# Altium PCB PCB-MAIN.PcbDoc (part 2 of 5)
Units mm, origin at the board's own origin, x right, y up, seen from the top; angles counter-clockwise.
Board outline 110 x 75 mm, 8 copper layers (F.Cu, In1.Cu, In2.Cu, In3.Cu, In4.Cu, In5.Cu, In6.Cu, B.Cu); 251 components, 185 nets, 1143 pads, 853 vias.
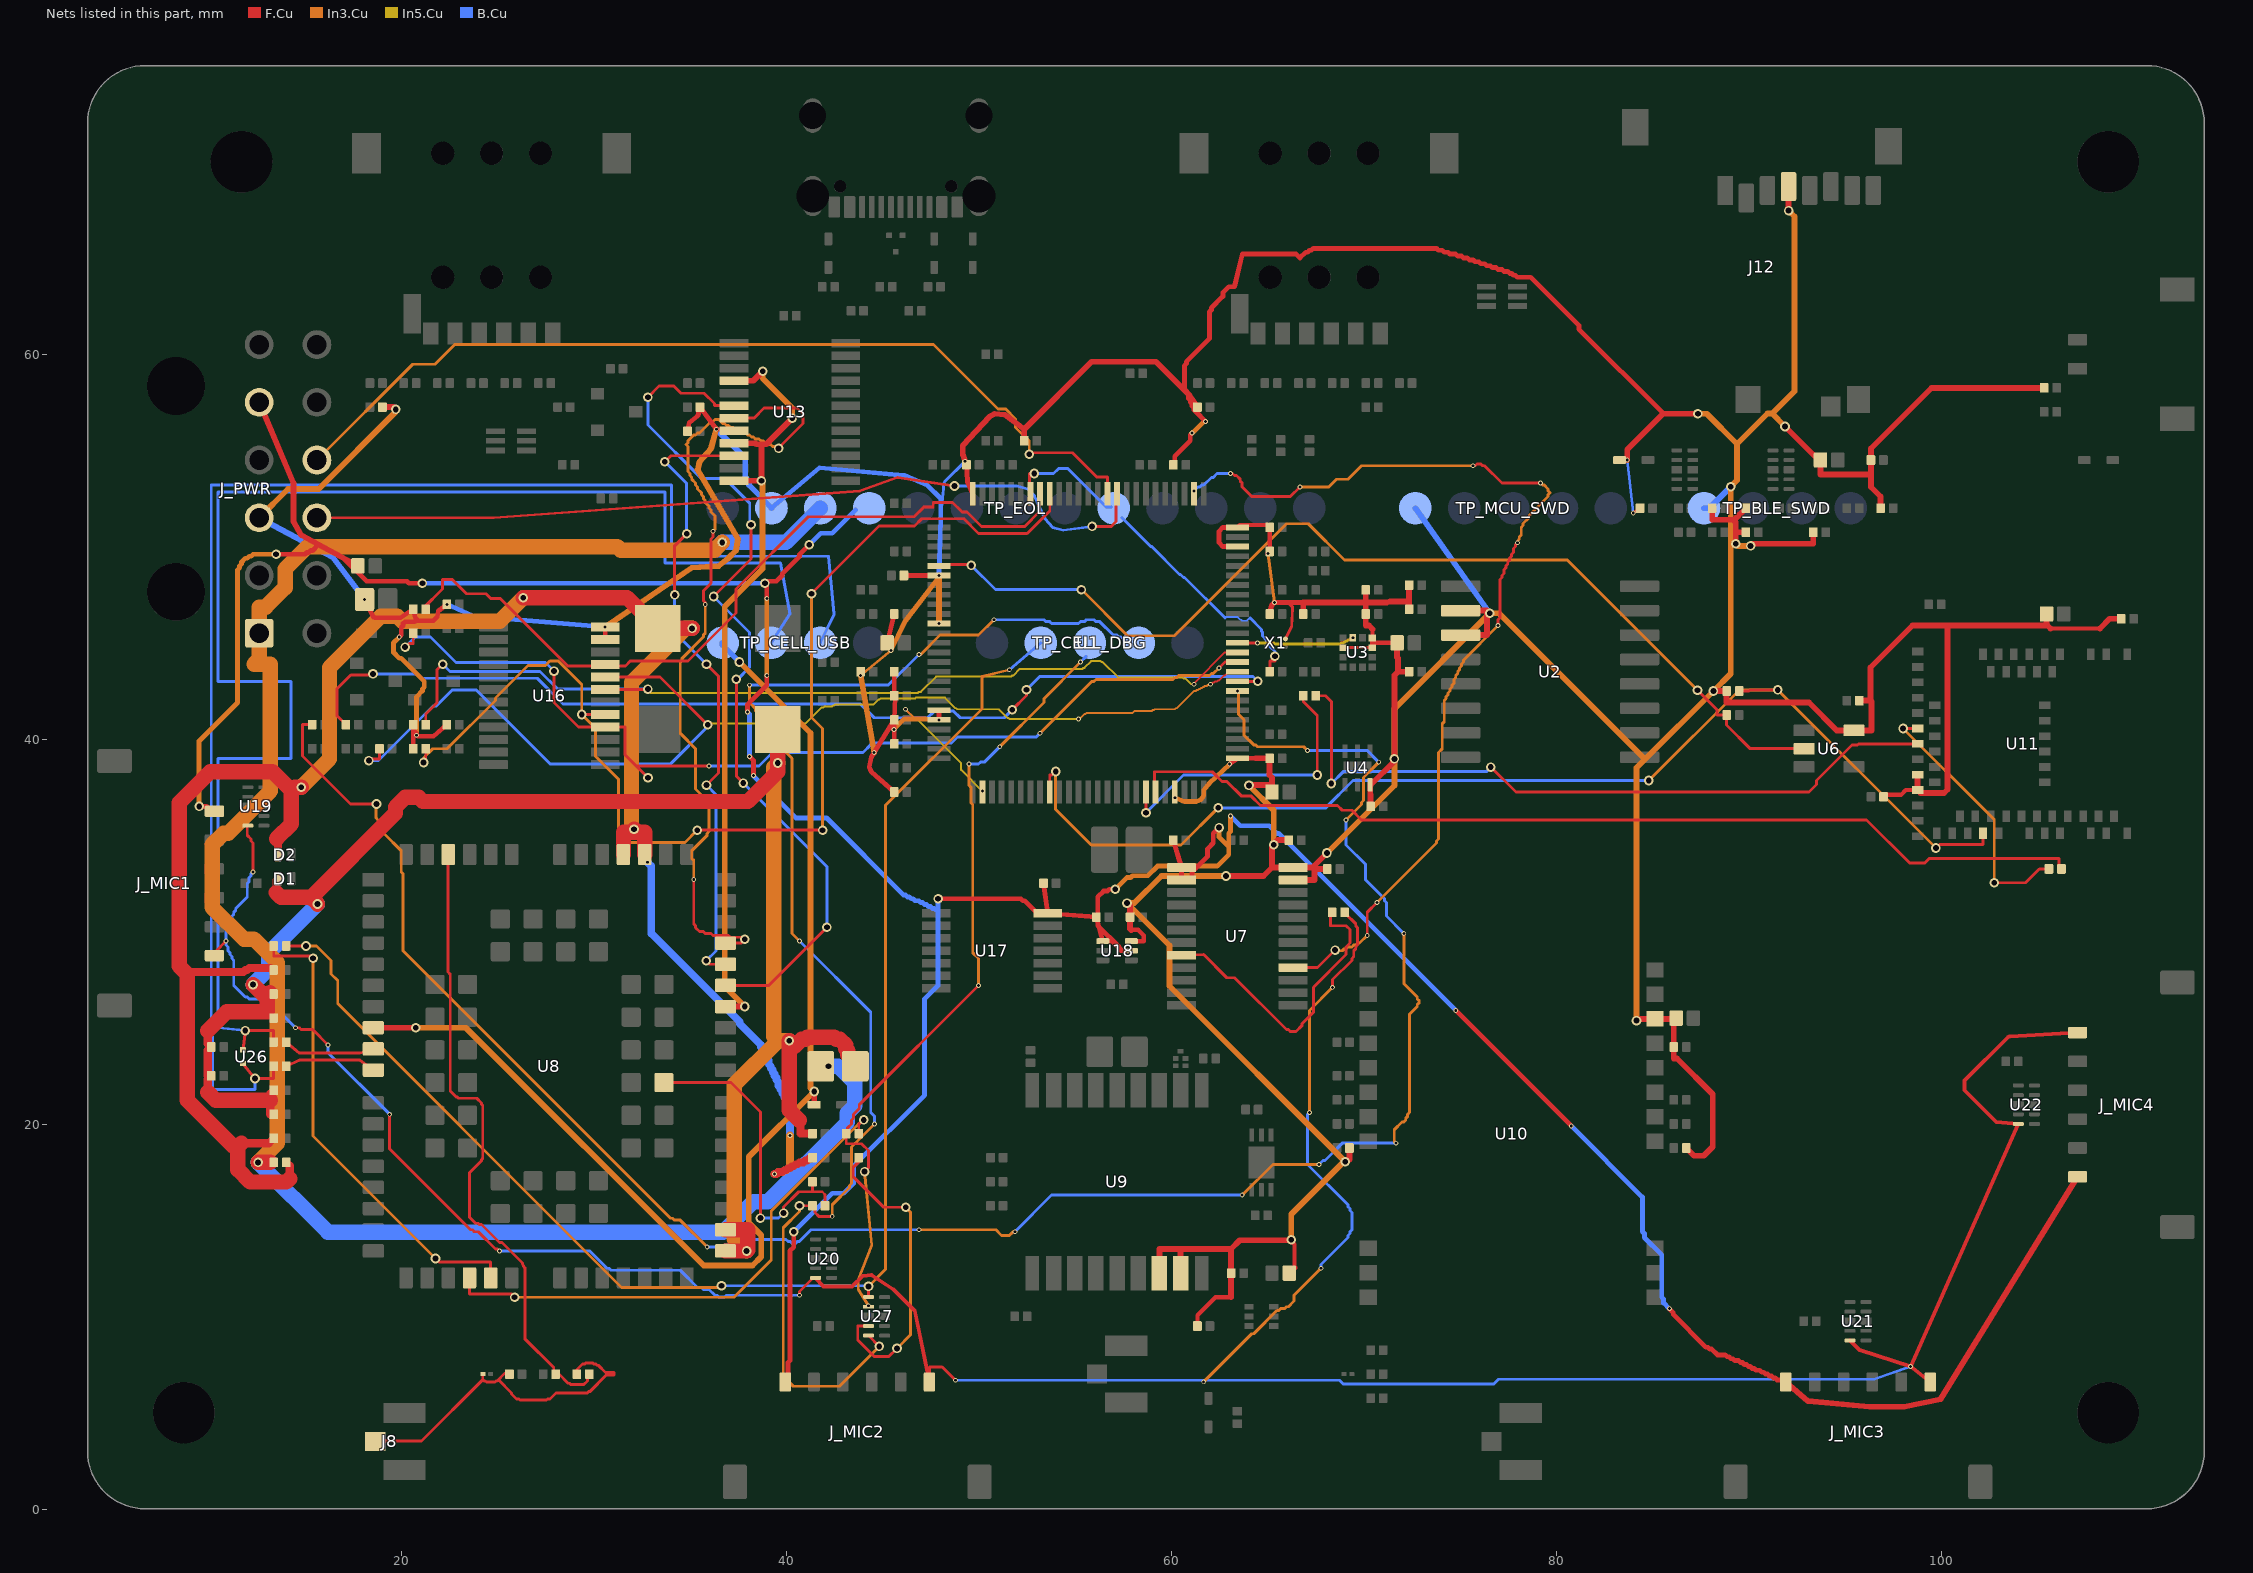
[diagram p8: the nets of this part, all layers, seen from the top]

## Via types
v1: diameter 0.5, hole 0.3, F.Cu to B.Cu, tented both sides, 579 vias
v2: diameter 0.25, hole 0.15, F.Cu to B.Cu, tented both sides, 274 vias

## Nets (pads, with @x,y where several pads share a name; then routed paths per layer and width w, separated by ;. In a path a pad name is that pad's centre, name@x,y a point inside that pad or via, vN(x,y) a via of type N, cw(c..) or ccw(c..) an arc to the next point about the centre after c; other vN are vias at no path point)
1V8_MIC: C20.1 C27.1 C30.1 C31.1 J_MIC1.1 J_MIC2.1 J_MIC3.1 J_MIC4.1 J_PWR.5 TP_EOL.4 U7.1 U7.2 U17.14 U18.1 U18.5 | length 207.4
  F.Cu w0.25: v1(9.485,36.525) 9.885,36.525 J_MIC1.1@9.985,36.425 ; v1(13.485,49.625) 14.985,49.625 15.085,49.725 15.185,49.725 15.285,49.825 15.385,49.825 15.685,50.125 ; 16.985,49.425 18.185,48.225 20.285,48.225 20.385,48.125 v1(21.085,48.125) ; v2(37.985,41.425) 37.985,41.825 38.985,42.825 v2(38.985,43.325) ; v2(38.085,39.125) 38.285,38.925 v2(38.285,38.125) ; v1(38.885,48.125) v1@38.985,48.225 ; v2(38.985,47.325) v1@38.985,48.225 ; J_MIC2.1@40.085,6.925 40.085,7.625 40.185,7.725 40.185,13.425 40.385,13.625 v1(40.385,14.425) ; v1(41.185,50.125) 40.685,49.625 40.685,49.525 39.785,48.625 39.785,48.525 39.485,48.225 v1@38.985,48.225 ; v1(47.885,31.725) 52.185,31.725 52.285,31.625 52.385,31.625 U17.14@52.985,31.025 ; C30.1@53.36,32.525 U17.14@53.585,30.975 C31.1@56.11,30.775 U18.1@56.445,29.525 56.945,29.525 57.445,29.025 U18.5@57.925,29.025 ; v1(57.085,32.225) 56.785,32.225 56.685,32.125 56.485,32.125 56.185,31.825 56.185,30.325 57.285,29.225 57.285,29.125 57.385,29.025 57.485,29.025 ; C27.1@60.11,34.775 U7.1@60.535,33.35 U7.2@60.535,32.7 ; U7.2@61.085,32.725 61.085,33.125 61.885,33.925 61.885,34.325 62.185,34.625 62.185,35.125 v1(62.485,35.425) ; v2(74.785,25.925) v2(80.785,19.925) ; v2(85.885,10.425) 86.085,10.225 86.085,10.125 87.785,8.425 87.885,8.425 87.985,8.325 88.085,8.325 88.385,8.025 88.785,8.025 88.885,7.925 88.985,7.925 89.085,7.825 89.185,7.825 89.285,7.725 89.485,7.725 89.585,7.625 89.685,7.625 89.785,7.525 89.885,7.525 89.985,7.425 90.085,7.425 90.185,7.325 90.285,7.325 90.385,7.225 90.585,7.225 90.685,7.125 90.785,7.125 90.885,7.025 90.985,7.025 91.085,6.925 91.185,6.925 91.285,6.825 91.385,6.825 91.485,6.725 91.685,6.725 J_MIC3.1@91.785,6.625
  F.Cu w0.3: J_PWR.5@12.605,57.525 14.385,53.325 14.385,51.325 14.785,50.625 C20.1@17.735,49.025 ; J_MIC3.1@91.935,6.615 93.085,5.625 96.285,5.325 98.085,5.325 99.985,5.725 J_MIC4.1@107.095,17.275
  In3.Cu w0.25: v1(9.485,36.525) 9.485,39.925 11.485,41.925 11.485,48.825 11.585,48.925 11.585,49.025 11.685,49.125 11.685,49.225 11.885,49.425 11.985,49.425 12.085,49.525 12.185,49.525 12.285,49.625 v1(13.485,49.625) ; v2(38.985,43.325) v2(38.985,47.325) ; v1(57.085,32.225) 57.685,32.825 57.885,32.825 57.985,32.925 58.785,32.925 59.285,33.425 62.385,33.425 62.985,34.025 62.985,34.425 ; v1(62.485,35.425) 62.485,34.925 62.985,34.425 ; v2(63.085,36.025) 63.085,35.225 62.985,35.125 62.985,34.425
  B.Cu w0.25: v1(21.085,48.125) v1(38.885,48.125) ; v2(37.985,41.425) 38.085,41.325 v2(38.085,39.125) ; v2(38.285,38.125) 40.485,35.925 42.085,35.925 46.085,31.925 46.185,31.925 46.285,31.825 46.385,31.825 46.485,31.725 46.585,31.725 46.685,31.625 46.885,31.625 46.985,31.525 47.085,31.525 47.185,31.425 47.285,31.425 47.385,31.325 47.485,31.325 47.585,31.225 47.685,31.225 47.785,31.125 47.885,31.125 ; v1(40.385,14.425) 42.385,16.425 42.985,16.425 43.485,16.925 43.485,17.825 47.185,21.525 47.185,26.525 47.885,27.225 v1(47.885,31.725) ; v1(41.185,50.125) 41.785,50.725 42.385,50.725 TP_EOL.4@43.585,51.925 ; v2(63.085,36.025) 63.585,35.525 65.085,35.525 65.485,35.125 65.585,35.125 v2(74.785,25.925) ; v2(80.785,19.925) 84.485,16.225 84.485,14.425 84.585,14.325 84.585,14.125 85.485,13.225 85.485,11.025 85.585,10.925 85.585,10.725 v2(85.885,10.425)
3V3_DIGITAL: C1.1 C2.1 C3.1 C4.1 C5.1 C6.1 C7.1 C8.1 C9.1 C10.1 C11.1 C12.1 C13.1 C19.1 C21.1 C22.1 C23.1 C24.1 C25.1 C26.1 C28.1 C29.1 C32.1 C34.1 C35.1 C49.1 C60.1 C61.1 C62.1 C66.1 C67.1 C71.1 C72.1 C73.1 C74.1 C75.1 D11.1 J12.4 J_PWR.3 R1.1 R4.1 R6.1 R7.1 R13.1 R14.1 R28.1 R32.1 R33.1 R44.1 R48.1 R49.1 R67.1 R68.1 R76.1 R78.1 R85.1 R86.1 R87.1 R88.1 R89.1 R90.1 R99.1 TP_BLE_SWD.1 TP_EOL.2 TP_MCU_SWD.1 U1.6 U1.11 U1.20 U1.21 U1.27 U1.47 U1.51 U1.73 U1.75 U1.100 U2.2 U2.3 U3.2 U3.9 U3.10 U4.3 U6.5 U7.23 U7.24 U9.7 U9.8 U10.9 U11.28 U11.30 U13.8 U16.23 U16.24 U18.6 X1.3 | length 470.8
  F.Cu w0.15: v2(43.86,43.325) R14.1@43.86,43.525 ; C6.1@45.235,45.025 v2(45.435,44.625) ; R1.1@65.11,46.525 65.31,47.025 65.41,47.075 66.11,47.075 66.31,46.875 66.26,45.875 X1.3@65.935,45.23 ; U3.2@68.922,44.775 U3.9@70.447,44.775 ; v2(84.01,51.775) R90.1@84.36,52.025
  F.Cu w0.225: U18.6@57.925,29.525 58.575,29.525 58.575,29.817 58.282,30.11 57.925,30.11 ; C62.1@61.36,9.525 61.36,10.09 62.295,11.025 63.11,11.025 ; U1.51@63.435,39.025 64.349,39.025 64.387,39.025 ; U1.75@63.435,51.025 63.56,51.15 64.985,51.15 C4.1@65.11,51.025 65.11,50.34 C12.1@65.11,49.775 ; v1@66.207,13.978 66.407,13.777 C61.1@66.407,12.548 ; v1@66.219,14.002 v1(66.231,14.002) ; U3.9@70.447,44.775 70.447,45.025 ; 70.46,45.737 70.46,45.288 U3.10@70.447,45.275 70.447,45.025 ; 71.2,47.124 71.31,47.124 71.36,47.175 ; C24.1@71.735,45.025 70.447,45.025 ; R78.1@97.01,37.125 97.921,37.125 98.171,37.375 U11.30@98.785,37.375 ; 105.684,45.774 108.26,45.774
  F.Cu w0.25: v2(18.085,47.275) 18.535,46.375 18.635,46.325 19.935,46.325 R32.1@20.61,46.775 20.71,46.325 20.86,46.175 ; v2(19.885,45.325) 19.985,45.425 19.985,45.825 20.085,45.925 20.085,46.025 20.185,46.125 20.685,46.125 20.785,46.225 20.86,46.175 ; R28.1@20.61,39.525 R33.1@20.61,40.775 20.66,40.425 ; v2(20.785,40.225) 20.785,40.325 20.66,40.425 ; C35.1@22.36,40.775 21.66,40.175 20.86,40.175 20.66,40.425 ; v2(22.36,47.025) 21.91,46.675 21.86,46.375 21.66,46.175 20.86,46.175 ; U16.23@30.585,45.2 v2(30.585,45.85) ; C49.1@34.86,56.025 34.96,56.475 35.41,56.825 R44.1@35.51,57.275 v2(36.36,56.125) U13.8@37.285,56.05 ; C6.1@45.235,45.025 C1.1@45.61,46.525 ; v2(45.585,40.525) C8.1@45.61,41.025 ; C2.1@45.61,37.275 44.41,38.325 44.31,38.575 44.41,39.075 C8.1@45.61,41.025 ; C10.1@45.61,39.775 C8.1@45.61,41.025 ; C11.1@45.61,43.525 C9.1@45.61,42.275 45.66,42.225 C8.1@45.61,41.025 ; C7.1@46.11,48.525 v2(47.935,48.525) ; v2(47.935,41.025) U1.20@47.935,41.525 ; C5.1@49.36,54.275 49.41,53.425 U1.100@49.685,52.775 ; R4.1@60.185,54.325 60.185,54.725 60.985,55.525 60.985,55.825 v2(61.085,55.925) ; R49.1@61.285,57.425 R49.1@61.285,57.025 ; v2(61.785,56.525) R49.1@61.285,57.025 ; v2(63.035,38.725) U1.51@63.435,39.025 ; U1.73@63.435,50.025 62.685,50.025 62.485,50.225 62.485,50.825 62.685,51.025 U1.75@63.435,51.025 ; v2(65.035,49.675) C12.1@65.11,49.775 ; R1.1@65.11,46.525 65.21,46.977 v2(65.36,47.127) 66.86,47.127 ; 85.585,56.925 81.185,61.325 81.185,61.525 78.685,64.025 77.985,64.025 77.885,64.125 77.785,64.125 77.685,64.225 77.585,64.225 77.485,64.325 77.285,64.325 77.185,64.425 76.985,64.425 76.885,64.525 76.685,64.525 76.585,64.625 76.385,64.625 76.285,64.725 76.085,64.725 75.985,64.825 75.785,64.825 75.685,64.925 75.485,64.925 75.385,65.025 75.185,65.025 75.085,65.125 74.885,65.125 74.785,65.225 74.485,65.225 74.385,65.325 74.185,65.325 74.085,65.425 73.885,65.425 73.785,65.525 67.385,65.525 67.285,65.425 67.185,65.425 67.085,65.325 66.985,65.325 66.685,65.025 66.485,65.225 63.685,65.225 63.285,63.525 62.985,63.525 62.685,63.225 62.685,63.025 62.085,62.425 62.085,62.325 61.985,62.225 61.985,60.825 60.785,59.625 60.785,59.525 60.685,59.425 60.685,58.225 60.785,58.125 60.785,58.025 60.885,57.925 60.885,57.725 60.985,57.625 60.985,57.525 61.085,57.425 61.085,57.325 61.185,57.225 61.185,57.125 R49.1@61.285,57.025
  F.Cu w0.3: R48.1@19.01,57.275 19.587,57.275 v1(19.704,57.158) ; C5.1@49.36,54.275 49.16,54.827 49.16,55.277 50.56,56.777 50.81,56.927 51.36,56.877 52.36,56.127 ; R6.1@52.36,55.525 52.36,56.127 ; v1(57.698,31.503) 57.825,31.377 57.86,31.377 C32.1@57.86,30.775 57.86,30.173 57.861,30.173 57.925,30.11 ; U9.7@59.385,12.275 59.385,13.527 60.485,13.527 ; U9.8@60.485,12.275 60.485,13.527 ; R49.1@61.36,57.275 60.955,57.877 59.205,59.627 55.86,59.627 52.36,56.127 ; v1(62.845,32.912) 64.795,32.912 65.233,33.35 ; 63.11,11.025 C60.1@63.11,12.275 63.11,13.527 ; v1(64.041,37.616) 64.062,37.638 C13.1@65.235,37.638 ; 64.387,39.025 64.533,39.025 C3.1@65.11,39.025 65.11,38.152 65.235,38.027 C13.1@65.235,37.638 ; C13.1@65.235,37.275 C13.1@65.235,37.638 ; C28.1@66.11,34.775 65.533,34.775 65.329,34.571 v1(65.329,34.533) 65.233,34.437 65.233,33.35 ; C61.1@66.135,12.275 C61.1@66.407,12.548 ; v1@66.219,14.002 66.207,13.99 66.207,13.978 63.561,13.978 63.11,13.527 ; U7.23@66.335,32.7 67.437,32.7 67.437,33.275 ; R13.1@66.86,46.525 66.86,47.127 70.11,47.127 ; v1(68.089,34.104) 67.335,33.351 ; C29.1@68.11,33.275 67.437,33.275 ; v1(69.042,18.059) 69.156,18.173 69.26,18.173 R67.1@69.26,18.775 ; C25.1@70.11,47.775 70.11,47.127 ; C26.1@70.36,36.525 70.36,37.127 70.335,37.152 U4.3@70.335,37.66 70.386,37.66 71.595,38.869 v1(71.595,38.995) 71.595,43.337 71.783,43.525 ; 70.46,45.737 70.274,45.923 70.11,45.923 C23.1@70.11,46.525 70.11,47.127 ; 71.2,47.124 71.197,47.127 70.11,47.127 ; 71.36,47.175 72.36,47.175 ; C24.1@71.735,45.025 71.735,44.273 71.783,44.225 71.783,43.525 ; R7.1@72.36,43.525 71.783,43.525 ; C21.1@72.36,46.775 72.36,47.175 ; C22.1@72.36,48.025 72.36,47.175 ; U2.3@75.035,45.43 76.412,45.43 v1@76.412,46.7 ; U2.2@75.035,46.7 v1@76.412,46.7 ; v1(76.555,46.56) 76.552,46.56 v1@76.412,46.7 ; D11.1@83.295,54.525 v2(83.695,54.525) 83.695,55.077 85.553,56.935 v1(87.368,56.935) ; v1(84.178,25.397) 84.245,25.397 84.333,25.485 U10.9@85.135,25.485 C67.1@85.937,25.485 ; C67.1@86.235,25.525 85.977,25.525 C67.1@85.937,25.485 ; R68.1@86.76,18.775 87.162,18.373 87.672,18.373 88.143,18.844 88.143,21.564 86.284,23.423 86.11,23.423 C66.1@86.11,24.025 86.11,25.312 C67.1@85.937,25.485 ; R86.1@88.11,52.025 88.11,51.423 89.206,51.423 89.232,51.397 ; v1(88.173,42.525) 88.283,42.525 R76.1@88.86,42.525 88.86,41.923 93.135,41.923 94.583,40.475 U6.5@95.485,40.475 96.387,40.475 96.387,41.975 96.337,42.025 ; v1(89.335,50.172) 89.337,50.174 89.337,50.775 ; R87.1@89.86,50.775 89.337,50.775 ; R89.1@89.86,52.025 89.232,51.397 ; v1(90.105,50.062) 90.216,50.173 93.36,50.173 R88.1@93.36,50.775 ; v1(91.894,56.268) 93.636,54.525 C75.1@93.735,54.525 93.735,53.773 96.36,53.773 ; v1(92.08,67.486) J12.4@92.08,68.735 ; C73.1@95.76,42.025 96.337,42.025 ; R85.1@96.86,52.025 96.86,52.627 96.36,53.127 96.36,53.773 ; R78.1@97.01,37.025 R78.1@97.01,37.125 ; U11.28@98.785,38.175 U11.30@98.785,37.375 98.937,37.223 100.159,37.223 100.337,37.402 100.337,45.923 ; R99.1@105.36,58.275 99.508,58.275 96.36,55.127 C74.1@96.36,54.525 96.36,53.773 ; C72.1@105.485,46.525 105.485,45.923 ; 105.684,45.774 105.536,45.923 105.485,45.923 ; 108.26,45.774 108.761,46.275 C71.1@109.36,46.275 ; 60.485,13.527 63.11,13.527 ; 65.233,33.35 U7.24@66.335,33.35 67.261,33.35 67.335,33.35 ; 67.335,33.35 67.437,33.35 67.437,33.275 ; 89.232,51.397 89.337,51.293 89.337,50.775 ; 96.337,42.025 96.337,43.741 98.518,45.923 100.337,45.923 ; 100.337,45.923 105.485,45.923
  In3.Cu w0.1: v2(46.185,41.575) 46.685,41.075
  In3.Cu w0.15: v2(43.86,43.325) v2(45.435,44.625) ; v2(65.035,49.675) v2(65.36,47.127)
  In3.Cu w0.25: v2(19.885,45.325) 19.585,45.025 19.585,44.525 19.885,44.225 19.985,44.225 21.185,43.025 21.185,42.725 21.085,42.625 21.085,42.525 20.785,42.225 v2(20.785,40.225) ; v2(45.435,44.625) 46.185,46.175 47.885,48.375 v2(47.935,48.525) ; v2(45.585,40.525) 46.135,41.075 46.335,41.075 47.235,41.075 v2(47.935,41.025) ; v2(60.185,36.975) 60.685,36.775 61.285,36.775 61.535,36.875 61.685,37.075 61.685,37.375 61.985,37.725 v2(63.035,38.725) ; v2(61.085,55.925) 61.685,56.525 v2(61.785,56.525)
  In3.Cu w0.3: J_PWR.3@12.605,51.525 14.105,53.025 15.696,53.025 19.704,57.034 v1(19.704,57.158) ; v2(30.585,45.85) 35.085,48.925 36.485,49.025 36.985,49.425 37.385,49.825 37.485,50.425 35.385,54.025 35.485,54.425 36.085,55.125 v2(36.36,56.125) ; v2(43.86,43.325) v2(44.562,39.322) ; v2(47.935,46.025) v2(47.935,48.525) ; v1(62.845,32.912) 59.488,32.912 58.079,31.503 v1(57.698,31.503) 59.91,29.291 59.91,27.188 68.96,18.138 v1@68.96,18.059 ; v1(64.041,37.616) 65.329,36.327 v1(65.329,34.533) ; v1(66.231,14.002) 66.231,15.33 v1@68.96,18.059 ; v1(68.089,34.104) 71.595,37.611 v1(71.595,38.995) 71.595,41.6 v1(76.555,46.56) 77.03,46.56 84.619,38.971 ; v1(69.042,18.059) v1@68.96,18.059 ; v1(84.178,25.397) 84.178,38.53 84.619,38.971 ; v1(87.368,56.935) 87.826,56.935 89.405,55.356 ; v1(90.105,50.062) 89.445,50.062 v1(89.335,50.172) 89.072,50.172 ; v1(91.894,56.268) 91.225,56.936 ; v1(92.08,67.486) 92.391,67.175 92.391,58.102 91.225,56.936 ; 84.619,38.971 v1(88.173,42.525) 89.072,43.424 89.072,50.172 ; 89.072,50.172 v1(89.072,53.139) 89.405,53.472 89.405,55.356 ; 89.405,55.356 90.986,56.936 91.225,56.936
  In5.Cu w0.1: v2(46.185,41.575) 46.735,41.025 46.835,41.025 49.085,38.775 49.085,38.425 v2(50.185,37.325)
  B.Cu w0.15: 48.025,51.525 48.185,53.325 48.235,53.425 v2(49.292,54.463) ; v2(83.695,54.525) v2(84.01,51.775)
  B.Cu w0.25: v2(22.36,47.025) 23.685,46.425 v2(30.585,45.85) ; TP_EOL.2@39.225,52.025 41.725,54.125 46.125,53.725 47.325,53.225 48.025,52.525 48.025,51.525 v2(47.935,48.525)
  B.Cu w0.3: J_PWR.3@12.605,51.525 16.435,49.475 v2(18.085,47.275) ; v2(36.36,56.125) 37.86,54.625 37.86,53.625 38.06,53.425 38.06,53.225 TP_EOL.2@39.225,52.025 ; TP_MCU_SWD.1@72.685,52.025 v1(76.555,46.56) ; TP_BLE_SWD.1@87.685,52.025 87.958,52.025 v1(89.072,53.139)
3V8_MODEM: FB1.1 J_PWR.1 R42.1 TP_EOL.3 | length 104.5
  F.Cu w0.4: R42.1@13.183,18.025 R42.1@13.36,18.025
  F.Cu w0.8: v1(12.549,18.025) R42.1@13.183,18.025
  In3.Cu w0.8: v1(12.549,18.025) 13.553,19.03 13.553,28.408 12.329,29.632 11.814,29.632 10.165,31.282 10.165,34.534 10.753,35.123 10.996,35.123 12.347,36.474 13.185,37.325 13.185,43.915 12.347,43.915 12.605,44.172 J_PWR.1@12.605,45.525 12.605,46.878 12.943,46.878 13.958,47.892 13.958,48.862 15.12,50.025 31.215,50.025 31.395,49.845 36.268,49.845 v1(36.666,50.243)
  B.Cu w0.8: v1(12.549,18.025) 16.173,14.401 36.714,14.401 38.299,15.986 39.039,15.986 43.165,20.112 43.165,20.589 43.555,20.979 43.555,22.156 42.685,23.025 v1(42.185,23.025) ; v1(36.666,50.243) 39.983,50.243 TP_EOL.3@41.765,52.025
3V8_MODEM_BB: C36.1 C37.1 C38.1 C39.1 C40.1 C41.1 C42.1 C43.1 D1.1 FB1.2 U8.32 U8.33 | length 93
  F.Cu w0.4: C37.1@9.934,22.35 C37.1@10.11,22.525 C37.1@9.935,22.525 ; C38.1@9.934,23.85 C38.1@10.11,24.025 C38.1@9.934,24.201 ; 13.022,25.863 C40.1@13.36,25.525 ; C39.1@13.184,21.6 C39.1@13.36,21.775 ; C41.1@13.185,20.525 C41.1@13.36,20.525 ; C43.1@13.227,26.775 C43.1@13.36,26.775 ; 40.661,20.224 40.733,20.152 40.733,19.525 C42.1@41.36,19.525
  F.Cu w0.401: 13.484,32.053 13.484,32.674 D1.1@13.585,32.775
  F.Cu w0.45: 9.934,21.673 C37.1@9.934,22.35 ; C37.1@9.934,22.525 C38.1@9.934,23.85 ; C38.1@9.934,24.201 9.934,24.877 ; C43.1@13.152,26.85 C43.1@13.227,26.775 ; C41.1@13.184,20.525 13.184,21.264 C39.1@13.184,21.6
  F.Cu w0.8: 9.934,21.673 10.343,21.264 13.184,21.264 ; 9.934,24.877 10.921,25.863 13.022,25.863 13.022,26.726 ; v1(12.283,27.268) 12.825,26.726 13.022,26.726 ; C43.1@13.152,26.85 13.028,26.726 13.022,26.726 ; 13.484,32.053 13.74,31.798 15.31,31.798 ; v1(15.636,31.451) 15.636,31.472 15.31,31.798 ; U8.32@36.835,13.425 v1(37.935,13.425) 37.987,13.477 37.987,14.525 U8.33@36.835,14.525 ; C36.1@39.555,40.525 v1(39.557,38.779) ; v1(39.557,38.779) v1(39.557,38.779) ; v1(40.145,24.346) 40.145,20.74 40.661,20.224 ; 40.385,24.025 40.785,24.425 40.985,24.425 41.085,24.525 42.485,24.525 42.585,24.425 42.785,24.425 43.085,24.125 43.085,23.925 43.185,23.825 FB1.2@43.185,23.625 ; 15.31,31.798 19.687,36.175 19.687,36.495 20.186,36.994 20.891,36.994 21.105,36.78 38.007,36.78 39.555,38.328 v1(39.557,38.779)
  In3.Cu w0.8: v1(37.935,13.425) 37.298,14.062 37.298,22.087 39.557,24.346 ; v1(39.557,38.779) 39.336,38.558 39.336,24.567 39.557,24.346 ; v1(40.145,24.346) 39.557,24.346
  B.Cu w0.8: v1(12.283,27.268) 13.088,28.072 13.088,28.901 v1(15.636,31.451) v1(15.636,31.451)
3V8_MODEM_RF: C44.1 C45.1 C46.1 C47.1 D2.1 R42.2 U8.52 U8.53 | length 107.6
  F.Cu w0.4: 9.085,27.925 11.785,27.925 11.885,28.025 11.985,28.025 12.085,28.125 13.185,28.125 C47.1@13.285,28.025 ; 13.11,19.025 C45.1@13.36,19.275 ; R42.2@14.01,18.025 R42.2@14.185,17.85 ; v2(39.385,17.425) 39.485,17.425 39.585,17.525 39.785,17.525 39.885,17.625 39.985,17.625 40.085,17.725 40.185,17.725 40.285,17.825 40.385,17.825 40.485,17.925 40.585,17.925 40.685,18.025 40.885,18.025 40.985,18.125 41.085,18.125 41.185,18.225 C46.1@41.285,18.225
  F.Cu w0.401: 13.511,34.851 13.585,34.777 D2.1@13.585,34.025
  F.Cu w0.45: 11.685,19.025 13.11,19.025 ; 14.185,17.173 R42.2@14.185,17.85
  F.Cu w0.8: 11.685,19.025 11.496,18.836 ; 13.511,34.851 14.275,35.615 14.275,37.351 ; 14.185,17.173 14.019,17.007 12.139,17.007 11.496,17.65 11.496,18.836 ; v1(14.795,37.527) 14.451,37.527 14.275,37.351 ; v1(26.328,47.373) 31.717,47.373 C44.1@33.315,45.775 v1(35.102,45.775) ; U8.53@31.535,34.025 31.535,35.177 v1@32.085,35.177 ; v1(32.085,35.338) v1@32.085,35.177 ; U8.52@32.635,34.025 32.635,35.177 v1@32.085,35.177 ; 11.496,18.836 11.295,18.836 8.876,21.255 8.876,27.802 8.445,28.233 8.445,36.708 10.071,38.335 13.291,38.335 14.275,37.351
  In3.Cu w0.4: v2(39.385,17.425) 39.485,17.425 39.585,17.525 39.785,17.525 39.885,17.625 39.985,17.625 40.185,17.825 v2(40.185,19.425)
  In3.Cu w0.8: v1(14.795,37.527) 16.26,38.992 16.26,43.746 18.926,46.412 19.778,46.412 20.038,46.153 25.108,46.153 v1(26.328,47.373) ; v1(32.085,35.338) 31.954,35.469 31.954,38.395 31.953,38.397 31.953,42.975 34.753,45.775 v1(35.102,45.775)
  B.Cu w0.4: v2(32.785,33.625) 32.985,33.425 32.985,29.925 37.585,25.325 37.585,25.225 38.685,24.125 38.685,24.025 38.785,23.925 38.785,23.825 38.885,23.725 38.885,23.625 38.985,23.525 38.985,23.425 39.085,23.325 39.085,23.125 39.185,23.025 39.185,22.925 39.285,22.825 39.285,22.725 39.385,22.625 39.385,22.525 39.485,22.425 39.485,22.325 39.585,22.225 39.585,22.025 39.685,21.925 39.685,21.825 39.785,21.725 39.785,21.625 39.885,21.525 39.885,21.425 39.985,21.325 39.985,21.225 40.085,21.125 40.085,20.925 40.185,20.825 v2(40.185,19.425)
AAD_CFG: U1.77 U7.16 | length 52.4
  F.Cu w0.15: v2(63.085,53.825) 63.185,53.825 63.285,53.725 63.385,53.725 63.585,53.525 63.585,53.425 63.685,53.325 63.685,53.125 64.185,52.625 66.185,52.625 v2(66.685,53.125) ; U7.16@66.335,28.15 67.604,28.15 v1(68.513,29.059) ; v2(70.185,29.825) 70.185,31.025 v2(70.685,31.525) ; v2(75.685,54.225) 75.785,54.225 75.885,54.325 76.085,54.325 76.185,54.225 76.285,54.225 77.185,53.325 v2(79.185,53.325) ; v2(76.985,45.925) 76.985,46.225 77.085,46.325 77.085,48.325 77.185,48.425 77.185,48.525 77.285,48.625 77.285,48.825 77.385,48.925 77.385,49.025 77.485,49.125 77.485,49.225 77.585,49.325 77.585,49.425 77.685,49.525 77.685,49.625 77.785,49.725 77.785,49.925 77.885,50.025 77.885,50.125 v2(77.985,50.225)
  In3.Cu w0.15: v2(66.685,53.125) 68.185,53.125 68.585,53.525 69.185,53.525 69.885,54.225 v2(75.685,54.225) ; v1@68.585,29.025 68.885,29.025 68.985,29.125 69.085,29.125 69.185,29.225 69.385,29.225 69.485,29.325 69.585,29.325 69.685,29.425 69.785,29.425 v2(70.185,29.825) ; v2(70.685,31.525) 73.785,34.625 73.785,34.725 73.885,34.825 73.885,39.325 74.085,39.525 74.085,40.825 74.185,40.925 74.185,42.025 74.285,42.125 74.285,42.225 74.385,42.325 74.385,42.425 74.485,42.525 74.485,42.625 74.585,42.725 74.585,42.825 74.685,42.925 74.685,43.125 74.785,43.225 74.785,43.325 74.885,43.425 74.885,43.525 74.985,43.625 74.985,43.725 75.085,43.825 75.085,43.925 75.185,44.025 75.185,44.125 v2(76.985,45.925) ; v2(77.985,50.225) 77.985,50.325 78.085,50.425 78.085,50.525 78.185,50.625 78.185,51.025 78.285,51.125 78.285,51.225 78.585,51.525 78.585,51.625 79.585,52.625 79.585,52.725 79.685,52.825 79.585,52.925 79.585,53.025 79.385,53.225 79.285,53.225 v2(79.185,53.325)
  B.Cu w0.15: v2(61.185,52.925) 61.385,53.125 61.485,53.125 61.585,53.225 61.685,53.225 62.085,53.625 62.185,53.625 62.385,53.825 v2(63.085,53.825)
AAD_CFG_1V8_FANOUT: J_MIC1.6 J_MIC2.6 J_MIC3.6 J_MIC4.6 R18.2 U19.5 U20.5 U21.5 U22.5 | length 170.6
  F.Cu w0.15: J_MIC1.6@10.385,28.925 10.385,29.025 v2(10.885,29.525) ; U19.5@11.985,35.525 11.985,35.025 12.185,34.825 12.185,34.725 12.285,34.625 v2(12.285,33.125) ; v2(14.485,25.025) 14.685,25.025 14.785,24.925 15.385,24.925 v2(16.185,24.125) ; v2(19.385,20.525) 19.385,18.725 23.585,14.525 23.685,14.525 23.785,14.425 23.985,14.425 24.885,13.525 24.985,13.525 v2(25.085,13.425) ; v2(40.685,11.125) 40.685,11.325 U20.5@41.385,12.025 ; J_MIC2.6@47.435,6.615 47.435,7.392 48.096,7.392 v2(48.783,6.705) ; v2(68.385,27.125) 68.385,27.525 69.385,28.525 69.385,28.625 69.485,28.725 69.485,29.025 69.585,29.125 69.585,29.225 69.685,29.325 69.685,30.225 69.585,30.325 69.585,30.425 R18.2@69.085,30.925
  F.Cu w0.2: U20.5@41.517,12.025 41.917,11.575 43.418,11.575 43.967,12.125 44.417,12.175 45.567,11.425 46.667,10.325 J_MIC2.6@47.435,6.615 ; U21.5@95.267,8.775 95.767,8.275 v2(98.417,7.425) ; J_MIC3.6@99.435,6.615 v2(98.417,7.425) ; J_MIC4.6@107.095,24.775 103.567,24.575 103.467,24.525 101.217,22.275 101.217,21.775 102.867,20.125 U22.5@104.017,20.025 v2(98.417,7.425)
  In3.Cu w0.15: v2(61.685,6.625) 64.185,9.125 64.285,9.125 65.485,10.325 65.585,10.325 65.685,10.425 65.885,10.425 65.985,10.525 66.085,10.525 66.385,10.825 66.385,11.125 v2(67.785,12.525) ; v2(67.185,20.625) 67.185,25.925 v2(68.385,27.125)
  B.Cu w0.15: v2(12.285,33.125) 12.185,33.025 12.185,32.925 12.085,32.825 12.085,32.625 11.985,32.525 11.985,31.825 11.385,31.225 11.385,31.125 11.285,31.025 11.285,30.925 11.185,30.825 11.185,30.725 11.085,30.625 11.085,30.425 10.985,30.325 10.985,30.225 10.885,30.125 v2(10.885,29.525) 10.885,29.325 10.985,29.225 10.985,29.025 11.085,28.925 11.085,28.825 11.185,28.725 11.185,28.625 11.285,28.525 11.285,27.225 11.885,26.625 11.985,26.625 12.085,26.525 12.985,26.525 v2(14.485,25.025) ; v2(16.185,24.125) 16.185,23.725 v2(19.385,20.525) ; v2(25.085,13.425) 29.785,13.425 30.685,12.525 30.785,12.525 30.885,12.425 34.485,12.425 35.385,11.525 35.585,11.525 35.685,11.425 35.985,11.425 36.285,11.125 36.385,11.125 36.485,11.025 36.785,11.025 36.885,11.125 v2(40.685,11.125) ; v2(48.783,6.705) 68.735,6.705 68.919,6.521 76.776,6.521 77.012,6.757 96.516,6.757 v2(98.417,7.425) ; 61.585,6.705 v2(61.685,6.625) ; v2(67.185,20.625) 67.085,20.525 67.085,17.925 69.185,15.825 69.185,15.725 69.285,15.625 69.285,15.525 69.385,15.425 69.385,14.525 69.285,14.425 69.285,14.325 69.185,14.225 69.185,14.125 67.785,12.725 v2(67.785,12.525)
AAD_CFG_1V8_U7: R18.1 U7.8 | length 15.7
  F.Cu w0.15: U7.8@60.535,28.8 61.685,28.825 62.885,27.625 63.285,27.625 65.985,24.925 66.085,24.925 66.185,24.825 66.485,24.825 66.785,25.125 66.785,25.225 67.385,25.825 67.385,27.125 69.085,28.825 69.085,29.225 69.285,29.425 69.285,30.125 69.085,30.325 68.385,30.325 68.285,30.325 R18.1@68.285,30.925
ACCEL_INT: U1.63 U3.12 | length 5.6
  F.Cu w0.15: U1.63@63.885,45.025 v2(64.485,45.025)
  In5.Cu w0.15: v2(64.485,45.025) 65.335,45.025 65.385,44.975 68.785,44.975 68.835,45.025 68.935,45.025 68.985,45.075 69.035,45.075 69.085,45.125 69.135,45.125 69.185,45.175 69.235,45.175 69.285,45.225 v2@69.335,45.225
  other v2: 69.435,45.288
BLE_DFU_REQ: R76.2 U1.34 U11.39 | length 61.6
  F.Cu w0.15: U1.34@53.685,37.275 53.685,38.152 53.806,38.152 v1(53.993,38.339) ; R76.2@89.51,42.525 90.012,42.525 90.067,42.58 v1(91.517,42.58) ; v1(99.735,34.363) 99.921,34.548 102.185,34.548 U11.39@102.185,35.125
  In3.Cu w0.15: v1(53.993,38.339) 53.993,36.367 55.847,34.513 60.503,34.513 v1(62.442,36.452) ; v1(84.813,37.87) 89.523,42.58 v1(91.517,42.58) v1(99.735,34.363)
  B.Cu w0.15: v1(62.442,36.452) 68.027,36.452 69.445,37.87 v1(84.813,37.87)
BLE_EN: R77.1 U1.5 U6.2 | length 54.2
  F.Cu w0.15: U1.5@47.935,49.025 48.008,49.098 49.558,49.098 v1(49.607,49.05) ; v1(87.345,42.563) 88.358,41.55 88.358,41.275 R77.1@88.86,41.275 88.86,40.748 90.083,39.525 U6.2@92.885,39.525
  In3.Cu w0.15: v1(55.33,47.79) 57.726,45.394 60.168,45.394 65.987,51.213 67.115,51.213 69.001,49.327 80.581,49.327 v1(87.345,42.563)
  B.Cu w0.15: v1(49.607,49.05) 50.867,47.79 v1(55.33,47.79)
BLE_RX_U1: R74.2 U1.45 | length 50.8
  F.Cu w0.15: U1.45@59.185,37.275 59.135,37.325 59.135,38.325 62.135,38.325 62.635,37.825 62.885,37.825 63.635,37.075 64.135,37.075 64.635,36.575 68.635,36.575 68.885,36.325 69.385,36.325 69.885,35.825 96.135,35.825 98.385,33.575 99.135,33.575 99.385,33.825 106.135,33.825 106.135,33.325 106.185,33.275 R74.2@106.26,33.275
BLE_RX_U11: R74.1 U11.22 | length 13.9
  F.Cu w0.15: v1(98.028,40.575) U11.22@98.785,40.575 ; v1(102.765,32.556) 104.389,32.556 105.108,33.275 R74.1@105.61,33.275
  In3.Cu w0.15: v1(98.028,40.575) 102.765,35.838 v1(102.765,32.556)
BLE_TX_U1: R75.1 U1.44 | length 15.2
  F.Cu w0.15: v1(58.685,36.199) U1.44@58.685,37.275 ; R75.1@66.86,42.275 66.86,41.985 67.589,41.256 v1(67.589,38.157)
  B.Cu w0.15: v1(58.685,36.199) 60.642,38.157 v1(67.589,38.157)
BLE_TX_U11: R75.2 U11.24 | length 37.7
  F.Cu w0.15: R75.2@67.51,42.275 68.012,42.275 68.32,41.968 v1(68.32,37.715) ; v1(76.606,38.568) 77.908,37.267 93.139,37.267 93.535,37.663 93.535,37.875 95.379,39.719 95.65,39.719 95.706,39.775 U11.24@98.785,39.775
  B.Cu w0.15: v1(68.32,37.715) 68.936,38.331 76.369,38.331 v1(76.606,38.568)
BOOT0: R2.1 TP_EOL.9 U1.94 | length 18.6
  F.Cu w0.15: U1.94@52.685,52.775 52.635,52.825 52.635,53.825 v1(52.885,53.825) ; R2.1@65.11,43.525 65.135,43.55 65.135,43.575 65.135,44.075 65.385,44.075 v1(65.385,44.325)
  B.Cu w0.1: 62.835,46.375 63.435,46.375 63.585,46.225 63.635,46.225 63.685,46.175 63.935,46.175 64.035,46.275
  B.Cu w0.15: v1(52.885,53.825) 53.885,53.825 54.135,54.075 54.635,54.075 56.635,52.075 TP_EOL.9@56.885,52.075 ; TP_EOL.9@57.435,51.525 58.935,50.025 58.985,50.025 60.435,48.575 60.485,48.575 60.635,48.425 60.685,48.425 62.785,46.325 ; 64.085,46.325 64.685,45.725 64.685,45.625 64.735,45.575 64.735,45.375 64.935,45.175 64.935,45.025 65.085,44.875 ; 65.135,44.825 65.385,44.575 v1(65.385,44.325)
CELL_DBG_RXD_TP: R37.1 TP_CELL_DBG.3 U27.2 | length 41
  F.Cu w0.15: R37.1@43.11,19.525 43.11,18.998 43.904,18.998 44.262,18.64 44.262,17.747 v1(44.065,17.55) ; R37.1@43.185,19.625 43.185,19.825 43.385,20.025 43.385,20.225 43.485,20.325 43.485,20.525 43.785,20.825 43.785,21.025 v2(49.985,27.225) ; U27.2@44.267,10.525 v2(44.267,10.575)
  In3.Cu w0.15: v1(44.065,17.55) 44.435,13.725 43.735,11.925 43.735,11.425 v2(44.267,10.575) ; v2(49.485,38.725) 49.485,37.625 49.585,37.525 49.585,36.725 49.685,36.625 49.685,28.925 49.985,28.625 v2(49.985,27.225) ; v2(51.085,39.625) 53.385,41.925 53.385,42.125 v2(55.285,44.025)
  B.Cu w0.15: v2(49.485,38.725) 49.985,38.725 50.085,38.825 50.285,38.825 v2(51.085,39.625) ; v2(55.285,44.025) TP_CELL_DBG.3@55.585,44.325
CELL_DBG_RXD_U8: R37.2 U8.22 | length 27.5
  F.Cu w0.15: U8.22@23.535,12.025 23.535,11.198 25.703,11.198 v1(25.879,11.022) ; R37.2@43.76,19.525 43.76,20.052 43.832,20.052 v1(44.016,20.236)
  In3.Cu w0.15: v1(25.879,11.022) 37.276,11.022 39.217,12.963 39.217,15.5 43.953,20.236 v1(44.016,20.236)
CELL_DBG_TXD_TP: R36.2 TP_CELL_DBG.2 U27.1 | length 77.1
  F.Cu w0.15: R36.2@14.01,29.275 v1(15.036,29.275) ; U27.1@44.267,11.025 v1(44.267,11.585)
  In3.Cu w0.15: v1(15.036,29.275) 15.576,29.275 16.334,28.517 16.334,27.824 16.685,27.474 16.685,26.279 23.062,19.902 23.062,19.893 31.432,11.523 36.531,11.523 v1(36.626,11.618) ; v1(44.267,11.585) 45.153,12.471 45.153,36.588 50.159,41.594 50.159,43.275 v2(51.585,43.625)
  B.Cu w0.15: v1(36.626,11.618) 44.235,11.618 v1(44.267,11.585) ; v2(51.585,43.625) TP_CELL_DBG.2@53.225,45.025
CELL_DBG_TXD_U8: R36.1 U8.23 | length 24.6
  F.Cu w0.15: R36.1@13.36,29.275 13.36,28.748 15.298,28.748 v1(15.405,28.641) ; v1(21.77,13.033) 21.95,12.852 24.635,12.852 U8.23@24.635,12.025
  In3.Cu w0.15: v1(15.405,28.641) 15.405,19.397 v1(21.77,13.033)
CELL_DBG_VREF_TP: R41.2 U27.4 | length 16.1
  F.Cu w0.15: R41.2@43.76,18.275 43.76,18.058 43.475,17.773 43.475,17.282 45.064,15.693 v1(46.2,15.693) ; U27.4@44.267,9.525 43.708,9.525 43.708,8.796 44.565,7.939 45.323,7.939 v1(45.747,8.363)
  In3.Cu w0.15: v1(45.747,8.363) 46.456,9.072 46.456,15.437 v1(46.2,15.693)
CELL_DTR_U16: R29.1 U1.61 U16.16 | length 51.7
  F.Cu w0.15: v1(20.188,44.803) 20.383,44.998 20.61,44.998 R29.1@20.61,45.525 ; v1(27.926,43.558) 27.926,41.926 29.202,40.65 29.558,40.65 U16.16@30.585,40.65 31.612,40.65 31.612,39.207 v1(32.809,38.01) ; 32.185,38.625 v2(35.985,38.625) ; v2(62.485,43.725) 62.785,44.025 U1.61@62.985,44.025
  In3.Cu w0.15: v2(53.185,40.325) 55.885,43.025 55.985,43.025 56.085,43.125 60.085,43.125 60.185,43.225 60.285,43.225 60.385,43.325 61.985,43.325 62.085,43.425 62.185,43.425 v2(62.485,43.725)
  B.Cu w0.15: v1(20.188,44.803) 20.712,45.327 21.503,45.327 22.83,44 27.484,44 v1(27.926,43.558) ; v2(35.985,38.625) 38.585,38.625 39.285,39.325 43.985,39.325 44.385,39.725 44.485,39.725 44.585,39.825 48.585,39.825 48.885,40.125 52.985,40.125 v2(53.185,40.325)
CELL_PWRKEY_CMD: R24.1 U1.58 | length 108.3
  F.Cu w0.15: R24.1@15.36,40.775 14.858,40.775 14.858,39.147 17.356,36.649 v1(18.698,36.649)
  In3.Cu w0.15: v1@18.685,36.525 18.685,35.925 18.785,35.825 18.785,35.725 18.885,35.625 18.885,35.525 18.985,35.425 18.985,35.325 19.085,35.225 19.085,35.125 19.985,34.225 19.985,33.125 20.085,33.025 20.085,29.025 33.985,15.125 34.085,15.125 34.185,15.025 34.485,15.025 v2(35.885,13.625) ; v2(46.885,14.525) 50.885,14.525 51.185,14.225 51.585,14.225 51.785,14.425 v2(51.885,14.425) ; v2@63.485,42.425 63.485,41.325 63.785,41.025 63.785,40.225 64.285,39.725 64.385,39.725 64.485,39.625 66.885,39.625 v2(67.085,39.425) ; v2(63.685,16.325) 65.285,17.925 v2(67.685,17.925) ; v2(69.085,35.825) 69.885,36.625 69.885,36.725 69.985,36.825 69.985,38.025 v2(70.785,38.825) ; v2(71.685,19.025) 71.585,19.125 71.585,19.725 71.985,20.125 72.085,20.125 72.185,20.225 72.185,20.325 72.285,20.425 72.285,20.525 72.385,20.625 72.385,25.725 72.785,26.125 72.785,26.225 72.885,26.325 72.885,26.425 72.785,26.525 72.785,26.625 72.085,27.325 v2(72.085,29.925)
  B.Cu w0.15: v2(35.885,13.625) 36.685,13.625 36.785,13.725 36.985,13.725 37.085,13.825 37.185,13.825 37.385,14.025 39.985,14.025 40.085,13.925 40.185,13.925 40.285,13.825 40.485,13.825 40.585,13.925 40.685,13.925 41.285,14.525 v2(46.885,14.525) ; v2(51.885,14.425) 53.785,16.325 v2(63.685,16.325) ; v2(67.085,39.425) 70.185,39.425 v2(70.785,38.825) ; v2(67.685,17.925) 67.885,18.125 67.985,18.125 68.885,19.025 v2(71.685,19.025) ; v2(69.085,35.825) 69.085,34.525 70.085,33.525 70.085,32.725 71.085,31.725 71.085,31.625 71.185,31.525 71.185,30.825 v2(72.085,29.925)
  other v2: 63.435,42.525
CELL_RESET_N_CMD: R26.1 U1.59 | length 53.7
  F.Cu w0.15: R26.1@17.11,40.775 16.649,41.236 16.649,42.64 17.367,43.358 18.467,43.358 v1(18.521,43.413) ; v1(51.737,41.548) 52.477,42.288 v1(52.477,42.584) ; U1.59@63.435,43.025 64.312,43.025 64.313,43.026 v1(64.491,43.026)
  B.Cu w0.15: v1(18.521,43.413) 20.836,43.413 21.062,43.186 27.055,43.186 28.387,41.855 43.844,41.855 44.567,41.131 47.335,41.131 47.685,41.475 48.685,41.475 49.035,41.131 51.321,41.131 v1(51.737,41.548) ; v1(52.477,42.584) 53.166,43.273 64.244,43.273 v1(64.491,43.026)
CELL_RF: C79.1 R43.1 U8.60 | length 33.1
  F.Cu w0.151: U8.60@22.41,34.05 22.41,27.925 22.535,27.8 22.535,21.738 22.847,21.425 22.91,21.425 22.972,21.362 23.91,21.362 24.16,21.113 24.16,21.05 24.222,20.988 24.222,18.238 24.16,18.175 24.16,18.113 23.535,17.488 23.535,15.175 23.847,14.863 23.972,14.863 24.035,14.8 24.16,14.8 25.097,13.863 25.222,13.863 26.285,12.8 26.285,12.738 26.347,12.675 26.347,12.613 26.41,12.55 26.41,8.863 27.91,7.362 27.91,7.175 28.035,7.05 28.16,7.05 28.66,6.55 28.722,6.55 28.785,6.488 29.472,6.488 29.66,6.675 29.66,6.925 R43.1@29.785,7.05
CELL_RF_ANT: C80.1 D3.1 J8.1 R43.2 | length 18.4
  F.Cu w0.151: J8.1@18.66,3.55 21.035,3.55 24.222,6.737 ; D3.1@24.222,7.05 24.222,6.737 ; 25.035,6.737 25.722,6.05 25.722,5.988 25.972,5.738 26.097,5.738 26.16,5.675 27.535,5.675 27.597,5.738 27.722,5.738 28.035,6.05 29.66,6.05 29.722,6.112 29.785,6.112 30.66,6.988 31.035,6.988 31.035,7.113 30.597,7.113 30.222,7.488 30.16,7.488 30.097,7.55 29.972,7.55 29.91,7.613 29.597,7.613 29.535,7.55 29.41,7.55 29.097,7.238 R43.2@29.097,7.05 ; C80.1@25.598,7.05 25.347,7.05 24.973,6.675 24.91,6.675 24.847,6.613 24.41,6.613 24.348,6.675 24.285,6.675 24.222,6.737
CELL_RI_U16: R33.2 U1.62 U16.19 | length 48.9
  F.Cu w0.1: v2(61.185,42.875) 61.185,42.925 62.785,44.525 U1.62@62.985,44.525
  F.Cu w0.15: R33.2@21.26,40.775 21.26,41.322 21.836,41.897 21.836,42.523 21.837,42.524 21.837,43.606 v1(22.144,43.913) ; U16.19@30.585,42.6 32.782,42.6 v1(32.804,42.622)
  In5.Cu w0.1: v1@32.885,42.475 32.935,42.425 46.835,42.425 46.885,42.475 46.985,42.475 47.785,43.275 51.685,43.275 51.735,43.325 51.785,43.325 52.135,43.675 55.385,43.675 55.435,43.725 55.485,43.725 55.835,44.075 56.335,44.075 56.385,44.025 56.435,44.025 57.235,43.225 60.585,43.225 60.635,43.175 60.735,43.175 61.035,42.875 v2(61.185,42.875)
  B.Cu w0.15: v1(22.144,43.913) 22.517,43.54 27.199,43.54 28.117,42.622 v1(32.804,42.622)
CELL_RX_U16: R32.2 U1.93 U16.21 | length 41.1
  F.Cu w0.15: R32.2@21.135,46.825 22.135,47.825 22.135,48.325 22.635,48.325 23.385,47.575 24.385,47.575 24.635,47.325 25.135,47.325 28.635,43.825 U16.21@30.635,43.825 ; U16.21@30.585,43.9 30.635,43.85 U16.21@30.635,43.825 ; U1.93@53.135,52.825 53.135,51.825 52.385,51.075 50.135,51.075 49.385,51.825 49.135,51.825 48.635,52.325 47.635,52.325 47.635,52.075 47.135,52.075 46.635,51.575 41.135,51.575 37.385,47.825 37.385,46.575 34.885,44.075 31.885,44.075 31.635,43.825 U16.21@30.635,43.825
CELL_STATUS_U16: R34.1 U1.60 U16.20 | length 58
  F.Cu w0.1: v2(62.035,42.875) 62.085,42.925 62.135,42.925 62.185,42.975 62.235,42.975 62.285,43.025 62.385,43.025 62.435,43.075 62.485,43.075 62.735,43.325 62.785,43.325 U1.60@62.985,43.525
  F.Cu w0.15: v1(18.307,38.905) 18.4,38.998 18.86,38.998 R34.1@18.86,39.525 ; U16.20@30.585,43.25 33.43,43.25 v1(35.916,40.764)
  In3.Cu w0.1: v2(55.185,41.075) 55.235,41.075 55.485,41.325 55.535,41.325 55.585,41.375 57.985,41.375 58.085,41.475 58.985,41.475 59.035,41.525 59.085,41.525 59.135,41.575 60.185,41.575 60.235,41.625 60.285,41.625 61.185,42.525 61.285,42.525 61.335,42.575 61.385,42.575 61.435,42.625 61.485,42.625 61.535,42.675 61.585,42.675 61.635,42.725 61.685,42.725 61.735,42.775 61.835,42.775 61.885,42.825 61.935,42.825 61.985,42.875 v2(62.035,42.875)
  In5.Cu w0.1: v1@36.085,40.825 40.985,40.825 41.835,41.675 41.935,41.675 41.985,41.725 42.385,41.725 42.435,41.775 42.485,41.775 42.535,41.825 44.535,41.825 44.785,42.075 44.835,42.075 44.885,42.125 46.685,42.125 46.735,42.175 48.235,42.175 48.785,41.625 48.835,41.625 48.885,41.575 51.035,41.575 51.485,41.125 51.535,41.125 51.585,41.075 v2(55.185,41.075)
  B.Cu w0.15: v1(18.307,38.905) 18.802,38.905 21.643,41.746 21.804,41.746 22.633,42.576 23.887,42.576 27.743,38.72 33.963,38.72 35.916,40.673 v1(35.916,40.764)
CELL_TX_U16: R28.2 U1.92 U16.17 | length 60.9
  F.Cu w0.15: v1(21.147,38.808) 21.26,38.921 R28.2@21.26,39.525 ; v1(29.366,41.3) U16.17@30.585,41.3 ; v1(35.365,35.292) v1(41.882,35.292) ; v1(41.307,47.582) 44.819,51.094 46.653,51.094 47.03,51.471 49.225,51.471 49.99,50.706 52.513,50.706 53.685,51.878 U1.92@53.685,52.775
  In3.Cu w0.15: v1(21.147,38.808) 21.147,39.042 21.627,39.521 22.363,39.521 24.877,42.035 24.877,42.159 26.574,43.856 27.478,43.856 27.708,44.085 28.144,44.085 29.366,42.863 v1(29.366,41.3) 30.091,40.575 30.091,39.126 31.277,37.94 31.277,35.167 31.793,34.652 34.725,34.652 v1(35.365,35.292) ; v1(41.307,47.582) 41.307,41.153 41.882,40.577 v1(41.882,35.292)
CELL_USB_BOOT_1V8: R35.1 R38.2 U8.75 | length 16.4
  F.Cu w0.112: 41.36,16.5 41.86,16.5 42.01,16.35
  F.Cu w0.15: U8.75@33.635,22.175 34.412,22.175 37.119,22.175 38.651,20.643 v1(38.651,15.134) ; v1(39.855,15.393) 39.855,15.709 40.645,16.5 41.36,16.5 R35.1@41.36,17.025 ; R38.2@42.01,15.775 42.01,16.35
  B.Cu w0.15: v1(38.651,15.134) 39.596,15.134 v1(39.855,15.393)
CELL_USB_BOOT_TP: R38.1 TP_CELL_DBG.4 U27.5 | length 70.8
  F.Cu w0.15: v1(40.681,15.775) R38.1@41.36,15.775 ; R38.1@41.385,15.725 41.385,15.625 41.485,15.525 41.485,15.425 41.685,15.225 v2(42.385,15.225) ; U27.5@44.267,9.025 v1(44.827,8.465)
  In3.Cu w0.15: v2(38.085,42.825) 38.085,41.925 38.385,41.625 38.385,41.525 38.485,41.425 38.485,40.825 40.285,39.025 40.285,29.925 v2(40.685,29.525) ; v1(40.681,15.775) 40.681,15.475 39.839,14.633 39.839,6.912 40.355,6.395 42.757,6.395 v1(44.827,8.465) ; v2(42.385,15.225) 42.385,15.825 43.285,16.725 43.285,16.825 43.385,16.925 43.385,18.825 v2(44.585,20.025) ; v2(46.885,44.425) 46.985,44.425 47.985,45.425 49.985,45.425 v2(50.785,46.225)
  B.Cu w0.15: v2(38.085,42.825) 45.285,42.825 v2(46.885,44.425) ; v2(40.685,29.525) 44.385,25.825 44.385,20.625 44.585,20.425 v2(44.585,20.025) ; v2(50.785,46.225) 53.385,46.225 53.485,46.125 53.685,46.125 53.785,46.025 55.185,46.025 55.285,46.125 55.485,46.125 55.585,46.225 55.985,46.225 56.085,46.125 56.285,46.125 56.985,45.425 57.185,45.425 57.285,45.325 57.385,45.325 TP_CELL_DBG.4@57.585,45.125
CELL_USB_DM_TP: R40.2 TP_CELL_USB.3 U26.2 | length 77.3
  F.Cu w0.154: U26.2@11.76,23.175 v1(12.385,22.384) 13.36,22.384 R40.2@13.36,23.025
  B.Cu w0.154: v1(12.385,22.384) 12.385,21.825 10.185,21.825 10.185,24.579 10.115,24.579 10.115,53.225 34.042,53.225 34.042,49.525 42.185,49.525 42.485,46.525 TP_CELL_USB.3@41.765,45.025
CELL_USB_DM_U8: R40.1 U8.10 | length 4.8
  F.Cu w0.154: R40.1@14.01,23.025 14.71,23.344 17.835,23.344 U8.10@18.535,22.825
CELL_USB_DP_TP: R39.2 TP_CELL_USB.2 U26.1 | length 77.3
  F.Cu w0.154: U26.1@11.76,23.875 v1(11.885,24.875) 13.36,24.875 R39.2@13.36,24.275
  B.Cu w0.154: v1(11.885,24.875) 10.472,25.025 10.472,39.025 14.257,39.025 14.257,43.025 10.472,43.025 10.472,52.868 33.685,52.868 33.685,49.168 39.685,49.168 40.185,46.525 TP_CELL_USB.2@39.225,45.025
CELL_USB_DP_U8: R39.1 U8.9 | length 4.8
  F.Cu w0.154: R39.1@14.01,24.275 14.71,23.701 17.835,23.701 U8.9@18.535,23.925
CELL_USB_VBUS: D10.1 TP_CELL_USB.1 U8.8 | length 61.7
  F.Cu w0.3: U8.8@18.535,25.025 v1(20.737,25.025) ; D10.1@41.445,21.025 v1(41.445,21.711)
  In3.Cu w0.3: v1(20.737,25.025) 23.341,25.025 35.704,12.663 38.238,12.663 38.696,13.121 38.696,14.239 38.05,14.885 38.05,18.315 v1(41.445,21.711) 41.256,21.9 41.256,40.336 v1(37.561,44.032)
  B.Cu w0.3: TP_CELL_USB.1@36.685,45.025 36.685,44.908 v1(37.561,44.032)
CELL_USIM_CLK_1V8: U8.46 U13.7 | length 43.6
  F.Cu w0.15: v2(35.185,32.725) 35.185,30.425 35.285,30.325 35.285,30.225 35.485,30.025 35.685,30.025 35.785,29.925 36.085,29.925 36.185,29.825 36.985,29.825 37.085,29.725 v1@37.785,29.725 ; v2(35.785,47.025) 35.785,47.125 35.685,47.225 35.685,47.725 36.085,48.125 36.085,50.425 36.185,50.525 v2(36.185,50.825) ; U8.46@36.835,29.425 37.662,29.425 37.662,29.448 v1(37.837,29.623) ; U13.7@37.285,56.7 38.312,56.7 38.837,57.225 40.554,57.225 40.861,56.918 40.861,56.418 39.595,55.152 v1(39.595,55.129)
  In3.Cu w0.15: v2(35.185,32.725) 35.185,33.725 35.085,33.825 35.085,34.225 35.885,35.025 35.885,35.125 35.985,35.225 35.985,36.725 35.285,37.425 35.285,39.525 34.485,40.325 34.485,44.025 34.585,44.125 34.585,44.225 35.685,45.325 35.685,45.425 35.785,45.525 v2(35.785,47.025) ; v2(36.185,50.825) 36.285,50.925 36.285,51.625 36.085,51.825 36.085,51.925 35.985,52.025 35.985,52.125 35.785,52.325 35.785,52.425 35.685,52.525 35.685,52.625 35.585,52.725 35.585,52.825 35.385,53.025 35.385,53.125 35.285,53.225 35.285,53.325 35.085,53.525 35.085,53.625 34.985,53.725 34.985,53.825 34.885,53.925 34.885,55.225 34.785,55.325 34.885,55.425 34.885,55.525 35.185,55.825 35.285,55.825 35.385,55.925 35.485,55.925 36.085,56.525 36.185,56.525 36.285,56.625 36.485,56.625 36.685,56.425 36.785,56.425 36.885,56.325 36.985,56.325 37.085,56.225 37.185,56.225 37.285,56.125 37.485,56.125 37.585,56.025 37.685,56.025 37.785,55.925 37.885,55.925 37.985,55.825 38.085,55.825 38.185,55.725 38.285,55.725 38.385,55.625 38.585,55.625 38.685,55.525 38.785,55.525 38.885,55.425 38.985,55.425 39.085,55.325 39.185,55.325 39.285,55.225 39.385,55.225 v1@39.485,55.125
CELL_USIM_DATA_1V8: U8.45 U13.10 | length 33.1
  F.Cu w0.15: v1(33.685,54.438) 33.997,54.75 U13.10@37.285,54.75 ; v1(34.196,47.517) 34.196,50.073 v1(34.82,50.697) ; v1(35.831,28.502) 36.008,28.325 U8.45@36.835,28.325 ; v1(35.848,37.633) 36.47,38.256 36.47,43.293 v1(35.848,43.916)
  B.Cu w0.15: v1(33.685,54.438) 34.82,53.303 v1(34.82,50.697) ; v1(34.196,47.517) 34.196,45.567 v1(35.848,43.916) ; v1(35.831,28.502) 36.349,29.02 36.349,37.131 v1(35.848,37.633)
CELL_USIM_RST_1V8: U8.44 U13.6 | length 46.1
  F.Cu w0.15: v1(32.804,57.79) 33.386,58.372 34.146,58.372 34.52,57.998 35.722,57.998 36.258,57.462 36.258,57.35 U13.6@37.285,57.35 ; v1(36.217,47.433) 38.161,49.377 v1(38.161,51.161) ; U8.44@36.835,27.225 39.081,27.225 v1(42.105,30.249) ; v1(37.401,43.137) 37.401,38.092 v1(37.758,37.735)
  B.Cu w0.15: v1(32.804,57.79) 32.804,56.349 35.579,53.575 36.799,53.575 38.098,52.276 38.098,51.224 v1(38.161,51.161) ; v1(36.217,47.433) 38.087,45.562 38.087,43.756 37.469,43.137 v1(37.401,43.137) ; v1(37.758,37.735) 42.105,33.388 v1(42.105,30.249)
CELL_USIM_VDD_1V8: U8.43 U13.4 U13.9 U13.12 | length 41.3
  F.Cu w0.3: U8.43@36.835,26.125 v1(37.837,26.125) ; U13.12@37.285,53.45 v1(38.703,53.45) 38.703,55.346 ; U13.9@37.285,55.4 38.387,55.4 38.44,55.346 38.703,55.346 ; U13.4@37.285,58.65 38.278,58.65 v1(38.768,59.14) ; v1(40.307,56.698) 38.955,55.346 38.703,55.346
  In3.Cu w0.3: v1(37.837,26.125) 36.799,27.163 36.799,46.918 38.763,48.881 38.763,53.39 v1(38.703,53.45) ; v1(38.768,59.14) 38.768,58.767 40.307,57.228 v1(40.307,56.698)
EN_AUX: J_PWR.10 U1.86 | length 48
  F.Cu w0.15: v1(52.622,54.821) 52.703,54.902 54.865,54.902 56.115,53.652 56.685,53.652 U1.86@56.685,52.775
  In3.Cu w0.15: J_PWR.10@15.605,54.525 20.584,59.504 21.746,59.504 22.764,60.522 47.651,60.522 50.994,57.178 51.399,57.178 51.913,56.664 51.913,56.212 52.622,55.503 v1(52.622,54.821)
EN_MODEM: J_PWR.9 U1.85 | length 44.5
  F.Cu w0.15: J_PWR.9@15.605,51.525 24.785,51.525 43.835,52.925 45.785,53.625 v1(48.735,53.175) ; v1(55.885,51.075) 56.885,51.075 57.135,51.325 U1.85@57.135,52.825
  B.Cu w0.15: v1(48.735,53.175) 51.985,53.175 52.535,53.025 52.885,52.675 53.435,51.475 53.835,51.025 54.385,50.875 v1(55.885,51.075)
